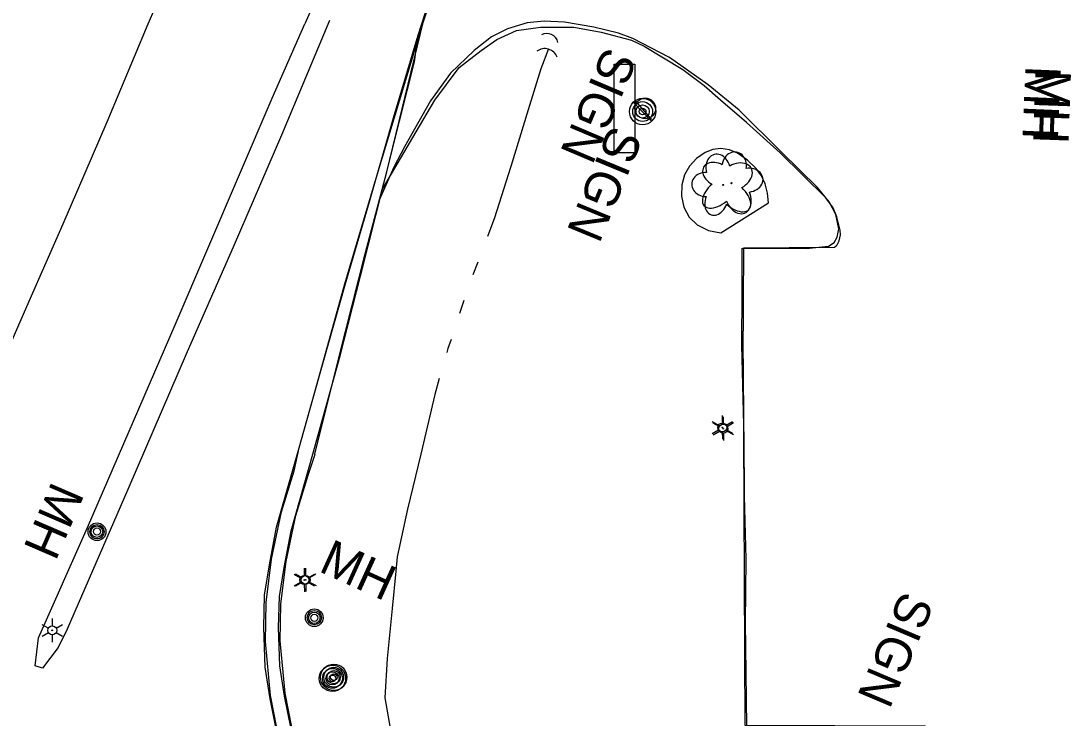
# Model space of a CAD drawing. Extents: x 588843 to 2552415, y 180129 to 269402.
# Drawn here: x 593439.1 to 593615.7, y 185837.6 to 185955.5 of the extents above; entities that cross this region are included whole.
import ezdxf

# ---------------------------------------------------------------- set-up
doc = ezdxf.new("R2010")
doc.units = 0
for name, color, linetype in [('Default', 7, 'Continuous'), ('E_DRN', 7, 'Continuous'), ('E_DWY', 7, 'Continuous'), ('E_LAND_Vegetation', 7, 'Continuous'), ('E_LTG', 7, 'Continuous'), ('E_MISCPROP', 7, 'Continuous'), ('E_MISCPROP_Planter', 7, 'Continuous'), ('E_RDWY', 7, 'Continuous'), ('E_RDWY_AsphConc', 7, 'Continuous'), ('E_RDWY_C_and_G', 7, 'Continuous'), ('E_RDWY_Gravel', 7, 'Continuous'), ('E_SGN', 7, 'Continuous'), ('E_SGN_Text', 7, 'Continuous'), ('E_UTL_MH', 7, 'Continuous'), ('E_UTL_MH_Text', 7, 'Continuous'), ('E_WTR_P', 7, 'Continuous')]:
    doc.layers.add(name, color=color, linetype=linetype)

# ---------------------------------------------------------------- blocks, each defined once
blk = doc.blocks.new('LPOL')
at = {"layer": 'Default'}
for p, q in [((-4, 0), (-1.5, 0)), ((-0.75, 1.3), (-2, 3.46)), ((0.75, 1.3), (2, 3.46)), ((1.5, 0), (4, 0)), ((-2, -3.46), (-0.75, -1.3)), ((2, -3.46), (0.75, -1.3))]:
    blk.add_line(p, q, dxfattribs=at)
for radius in [1.5, 1.5, 1.5, 0.125]:
    blk.add_circle((0, 0), radius, dxfattribs=at)
blk = doc.blocks.new('POLE')
at = {"layer": 'Default'}
for radius in [4.46, 3.35, 2.23, 1.12]:
    blk.add_circle((0, 0), radius, dxfattribs=at)
blk = doc.blocks.new('MHO')
at = {"layer": 'Default'}
for centre, radius in [((0.08, -0.12), 3), ((0.08, -0.12), 2.43), ((0.07, -0.15), 1.94), ((0.02, -0.16), 1.21)]:
    blk.add_circle(centre, radius, dxfattribs=at)
blk = doc.blocks.new('MHT')
at = {"layer": 'E_UTL_MH_Text'}
blk.add_text('MH', height=12, dxfattribs=at).set_placement((-9.81, -6))
blk = doc.blocks.new('SIGN')
at = {"layer": 'Default'}
blk.add_text('SIGN', height=12, dxfattribs=at).set_placement((-18.55, -6))
blk = doc.blocks.new('CULV2')
at = {"layer": 'E_DRN'}
blk.add_arc((19.7, 14.8), 24.6, 216.8699, 323.1301, dxfattribs=at)
blk = doc.blocks.new('DTRE_1_1')
at = {"layer": 'Default'}
blk.add_circle((-0.18, 0), 0.183, dxfattribs=at)
for centre, major_axis, ratio in [((-1.87, 5.32), (1.36, -4.98), 0.782863), ((4.06, 2.74), (-5.27, -2.93), 0.691916), ((-5.87, 0.15), (4.93, -0.12), 0.832022), ((3.54, -3.71), (-5.01, 4.58), 0.560249), ((-2.49, -5.24), (1.8, 4.86), 0.716896)]:
    blk.add_ellipse(centre, major_axis=major_axis, ratio=ratio, start_param=1.570796, end_param=4.712389, dxfattribs=at)
blk = doc.blocks.new('SGN_1')
at = {"layer": 'Default'}
blk.add_lwpolyline([(-3.5, -15), (-10.5, -15), (-10.5, 15), (-3.5, 15)], close=True, dxfattribs=at)
blk.add_circle((0, 0), 3.5, dxfattribs=at)
blk = doc.blocks.new('CULV2_4')
at = {"layer": 'E_DRN'}
blk.add_arc((64.6, 48.4), 80.7, 216.8699, 323.1301, dxfattribs=at)
blk = doc.blocks.new('MHO_3')
at = {"layer": 'E_UTL_MH'}
for centre, radius in [((0.3, -0.4), 9.84), ((0.3, -0.4), 7.98), ((0.2, -0.5), 6.35), ((0.1, -0.5), 3.97)]:
    blk.add_circle(centre, radius, dxfattribs=at)
blk = doc.blocks.new('MHT_3')
at = {"layer": 'E_UTL_MH_Text'}
blk.add_text('MH', height=39.37, dxfattribs=at).set_placement((-32.2, -19.7))
blk = doc.blocks.new('LPOL_4')
at = {"layer": 'E_LTG'}
for p, q in [((-13.1, 0), (-4.9, 0)), ((-2.5, 4.3), (-6.6, 11.4)), ((2.5, 4.3), (6.6, 11.4)), ((4.9, 0), (13.1, 0)), ((-6.6, -11.4), (-2.5, -4.3)), ((6.6, -11.4), (2.5, -4.3))]:
    blk.add_line(p, q, dxfattribs=at)
for radius in [4.92, 4.92, 4.92, 0.41]:
    blk.add_circle((0, 0), radius, dxfattribs=at)
blk = doc.blocks.new('POLE_3')
at = {"layer": 'E_MISCPROP'}
for radius in [14.6, 11, 7.32, 3.66]:
    blk.add_circle((0, 0), radius, dxfattribs=at)
blk = doc.blocks.new('SIGN_3')
at = {"layer": 'E_SGN'}
blk.add_text('SIGN', height=39.37, dxfattribs=at).set_placement((-56.1, -19.7))
blk = doc.blocks.new('DTRE_4')
at = {"layer": 'E_LAND_Vegetation'}
blk.add_circle((-0.6, 0), 0.601, dxfattribs=at)
for centre, major_axis, ratio in [((-6.1, 17.5), (4.5, -16.3), 0.782863), ((13.3, 9), (-17.3, -9.6), 0.691916), ((-19.3, 0.5), (16.2, -0.4), 0.832022), ((11.6, -12.2), (-16.4, 15), 0.560249), ((-8.2, -17.2), (5.9, 15.9), 0.716896)]:
    blk.add_ellipse(centre, major_axis=major_axis, ratio=ratio, start_param=1.570796, end_param=4.712389, dxfattribs=at)

msp = doc.modelspace()

# ---------------------------------------------------------------- linework, layer by layer
at = {"layer": 'E_DWY'}
for points in [[(593561.94, 185836.17), (593561.79, 185845.33), (593561.7, 185853.71), (593561.78, 185864.51), (593561.53, 185875.2), (593561.46, 185884.92), (593561.05, 185900.77), (593561.15, 185909.64), (593561.13, 185917.12), (593571.94, 185917.04), (593575.75, 185917.43), (593576.69, 185918.07), (593577.21, 185918.97), (593577.49, 185920.35), (593576.96, 185922.82), (593575.82, 185924.96), (593573.84, 185927.35), (593567.73, 185933.39), (593560.63, 185940.47), (593555.38, 185944.71), (593548.82, 185949.37), (593542.62, 185952.54), (593540.2, 185953.46), (593536.05, 185954.48), (593531.09, 185955.31), (593527.62, 185955.49), (593524.78, 185955.24), (593521.41, 185954.22), (593518.74, 185952.83), (593515.8, 185950.54), (593511.77, 185946.7), (593508.42, 185942.02), (593503.99, 185934.26), (593502.21, 185930.8), (593499.75, 185925.22)], [(593500.29, 185927.09), (593505.98, 185936.79), (593509.15, 185942.13), (593513.24, 185947.65), (593516.99, 185950.55), (593519.61, 185952.39), (593522.93, 185953.92), (593527.03, 185954.47), (593532.67, 185954.47), (593537.25, 185953.63), (593542.38, 185952.3), (593544.53, 185951.27)], [(593561.3, 185898.37), (593561.59, 185836.43), (593592.09, 185836.3), (593585.32, 185824.31), (593579.2, 185807.78), (593629.08, 185786.97), (593683.34, 185763.77), (593715.78, 185763.83), (593758.03, 185763.57), (593758.13, 185803.19), (593757.72, 185847.98), (593757.71, 185903.71), (593757.53, 185954.3)]]:
    msp.add_lwpolyline(points, dxfattribs=at)
at = {"layer": 'E_MISCPROP_Planter'}
msp.add_lwpolyline([(593565.57, 185924.78), (593565.42, 185926.41), (593565.01, 185927.99), (593565.01, 185927.99), (593564.38, 185929.35), (593563.51, 185930.58), (593563.51, 185930.58), (593562.04, 185932.01), (593560.34, 185933.17), (593560.34, 185933.17), (593558.98, 185933.73), (593557.52, 185933.94), (593557.52, 185933.94), (593556.15, 185933.78), (593554.86, 185933.27), (593554.86, 185933.27), (593553.42, 185932.26), (593552.23, 185930.98), (593552.23, 185930.98), (593551.38, 185929.49), (593550.93, 185927.83), (593550.93, 185927.83), (593550.89, 185925.92), (593551.28, 185924.05), (593551.28, 185924.05), (593552.16, 185922.36), (593553.53, 185921.03), (593553.53, 185921.03), (593555.44, 185920.08), (593557.53, 185919.71), (593557.53, 185919.71)], close=True, dxfattribs=at)
at = {"layer": 'E_RDWY'}
for points in [[(593486.2, 185883.3), (593489.18, 185893.96), (593493.89, 185911.07), (593499.24, 185928.93), (593507.1, 185955.12), (593509.61, 185962.65), (593517.48, 185983.79), (593527.72, 186012.54), (593531.1, 186022.16), (593535.59, 186036.96), (593539.47, 186051.68), (593541.2, 186062.67), (593545.15, 186089.33), (593548.03, 186107.77), (593551.11, 186127.76), (593554.74, 186154.6), (593556.82, 186170.65)], [(593460.64, 185955.04), (593467.37, 185970.47), (593472.37, 185982.97), (593477.68, 185995.79), (593482.62, 186008.82), (593487.75, 186022.71), (593492.35, 186036.69), (593496.3, 186049.62), (593500.01, 186061.89)], [(593522.56, 186054.59), (593521.25, 186049.62), (593517.22, 186036.16), (593512.49, 186021.93), (593508.45, 186009.64), (593504.16, 185997.05), (593500.25, 185987.06), (593494.6, 185972.85), (593489.15, 185959.57), (593487.18, 185955.06)], [(593506.3, 185953.15), (593509.39, 185962.62), (593513.59, 185974.38), (593520.05, 185991.23), (593526.18, 186009.1), (593530.36, 186021.24), (593534.44, 186034.67), (593538.07, 186046.79), (593539.46, 186052.49)], [(593491.32, 185955.6), (593483.2, 185936.21), (593475.03, 185917.29), (593467.27, 185899.56), (593457.19, 185876.3), (593446.96, 185852.66), (593445.45, 185849.57), (593442.79, 185846.03), (593441.53, 185846.44), (593442.11, 185851.19), (593450.4, 185869.87), (593465.24, 185904.11), (593481.63, 185942.45), (593487.18, 185955.06)], [(593426.69, 185881.38), (593434.16, 185893.64), (593440.51, 185908.11), (593446.3, 185921.2), (593453.72, 185938.48), (593460.64, 185955.04)], [(593486.07, 185882.94), (593490.12, 185897.35), (593494.11, 185911.31), (593497.9, 185924.36), (593502.15, 185939.12), (593506.3, 185953.15)]]:
    msp.add_lwpolyline(points, dxfattribs=at)
at = {"layer": 'E_RDWY_AsphConc'}
for points in [[(593575.28, 185925.62), (593567.53, 185933.21), (593567.53, 185933.21), (593561.85, 185938.36), (593561.85, 185938.36), (593557.47, 185942.16), (593557.47, 185942.16), (593554.67, 185944.56), (593554.67, 185944.56), (593551.1, 185947.24), (593551.1, 185947.24), (593544.53, 185951.21), (593544.53, 185951.21)], [(593561.32, 185898.38), (593561.43, 185917.13), (593576.75, 185917.25), (593577.04, 185917.48), (593577.04, 185917.48), (593577.19, 185917.64), (593577.19, 185917.64), (593577.55, 185918.35), (593577.55, 185918.35), (593577.76, 185919.33), (593577.76, 185919.33), (593577.71, 185920.14), (593577.71, 185920.14), (593577.15, 185922.41), (593577.15, 185922.41), (593576.5, 185923.9), (593576.5, 185923.9), (593575.28, 185925.62), (593575.28, 185925.62)]]:
    msp.add_lwpolyline(points, dxfattribs=at)
at = {"layer": 'E_RDWY_C_and_G'}
for points in [[(593524.54, 185785.23), (593520.46, 185787.18), (593514.54, 185790.64), (593509.77, 185793.89), (593504.56, 185798.16), (593499.13, 185803.52), (593495.33, 185808.28), (593491.66, 185813.55), (593488.12, 185819.59), (593485.79, 185824.76), (593484.01, 185829.67), (593482.39, 185835.21), (593481.28, 185840.87), (593480.44, 185846.23), (593480.21, 185852.92), (593480.35, 185858.38), (593481.19, 185863.53), (593482.38, 185869.88), (593486.07, 185882.94)], [(593525.28, 185784.5), (593516.08, 185789.89), (593507.12, 185796.18), (593500.49, 185802.26), (593495.89, 185807.55), (593491.73, 185813.52), (593488.45, 185819.36), (593485.74, 185825.44), (593482.99, 185833.08), (593481.36, 185841.45), (593480.5, 185850.56), (593480.6, 185857.14), (593481.52, 185864.5), (593483.18, 185872.5), (593485.32, 185879.46), (593486.2, 185883.3)], [(593525.62, 185787.49), (593521.63, 185789.39), (593515.87, 185792.75), (593511.27, 185795.89), (593506.24, 185800.02), (593501, 185805.19), (593497.34, 185809.78), (593493.77, 185814.9), (593490.34, 185820.74), (593488.11, 185825.7), (593486.38, 185830.45), (593484.82, 185835.81), (593483.74, 185841.3), (593482.93, 185846.46), (593482.71, 185852.93), (593482.84, 185858.15), (593483.65, 185863.1), (593484.82, 185869.31), (593488.48, 185882.26)], [(593526.49, 185787.32), (593517.38, 185792.03), (593508.69, 185798.13), (593502.28, 185804.01), (593497.86, 185809.09), (593493.85, 185814.85), (593490.68, 185820.48), (593488.06, 185826.38), (593485.4, 185833.75), (593483.84, 185841.81), (593483, 185850.66), (593483.1, 185856.96), (593483.98, 185864.09), (593485.61, 185871.88), (593487.7, 185878.69), (593488.91, 185882.24)]]:
    msp.add_lwpolyline(points, dxfattribs=at)
at = {"layer": 'E_RDWY_Gravel'}
for points in [[(593488.82, 185882.27), (593492.95, 185898.78), (593497.36, 185916.15), (593501.01, 185930), (593507.22, 185955.48)], [(593488.48, 185882.26), (593493.13, 185898.88), (593496.57, 185912.37), (593500.46, 185927.75), (593501.95, 185933.67), (593505.72, 185948.6), (593506.3, 185953.15)]]:
    msp.add_lwpolyline(points, dxfattribs=at)
at = {"layer": 'E_SGN'}
msp.add_line((593542.99, 185942.1), (593545.78, 185938.85), dxfattribs=at)
msp.add_lwpolyline([(593545.86, 185938.52), (593542.72, 185941.73)], dxfattribs=at)
at = {"layer": 'E_WTR_P'}
for points in [[(593528.34, 185950.83), (593527.05, 185947.41), (593524.91, 185940.5), (593521.98, 185930.9), (593519.17, 185922.06), (593518.03, 185919.05)], [(593516.39, 185914.74), (593515.57, 185912.58)], [(593514.06, 185908.23), (593513.33, 185906.04)], [(593511.88, 185901.66), (593511.36, 185900.1), (593511.18, 185899.47)], [(593509.9, 185895.03), (593509.12, 185892.32), (593506.77, 185882.26), (593504.49, 185872.96), (593502.78, 185864.91), (593502.54, 185862.44)], [(593502.54, 185862.44), (593501.94, 185856.15), (593501.07, 185847.66), (593500.71, 185841.06), (593501.59, 185835.88), (593503.3, 185829.7), (593503.38, 185829.42)]]:
    msp.add_lwpolyline(points, dxfattribs=at)

# ---------------------------------------------------------------- block references
at = {"layer": 'E_DRN'}
for name, p, xscale, yscale, rotation in [('CULV2', (593529.97, 185951.92), 0.07740257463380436, 0.07740257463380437, 155.57690095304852), ('CULV2_4', (593529.84, 185949.39), 0.027930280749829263, 0.027930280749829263, 163.57397236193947)]:
    msp.add_blockref(name, p, dxfattribs=dict(at, xscale=xscale, yscale=yscale, rotation=rotation))
at = {"layer": 'E_LAND_Vegetation', "xscale": 0.5, "yscale": 0.5}
msp.add_blockref('DTRE_1_1', (593558, 185927.8), dxfattribs=at)
at = {"layer": 'E_LAND_Vegetation', "xscale": 0.1524003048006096, "yscale": 0.1524003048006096, "rotation": -97.36026881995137}
msp.add_blockref('DTRE_4', (593559.32, 185928.01), dxfattribs=at)
at = {"layer": 'E_LTG'}
for name, p, xscale, yscale, rotation in [('LPOL', (593557.76, 185886.77), 0.5000000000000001, 0.5, -89.67337617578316), ('LPOL_4', (593557.93, 185886.56), 0.1524003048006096, 0.1524003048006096, -89.2544447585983), ('LPOL', (593487.06, 185860.97), 0.5000000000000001, 0.5, -89.67337617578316), ('LPOL_4', (593487.3, 185861), 0.1524003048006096, 0.1524003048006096, -89.2544447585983), ('LPOL', (593444.43, 185852.45), 0.5000000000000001, 0.5, -89.67337617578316)]:
    msp.add_blockref(name, p, dxfattribs=dict(at, xscale=xscale, yscale=yscale, rotation=rotation))
at = {"layer": 'E_MISCPROP'}
for name, p, xscale, yscale, rotation in [('POLE', (593544.29, 185940.21), 0.5000000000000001, 0.5, -92.40976933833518), ('POLE', (593491.82, 185844.33), 0.5000000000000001, 0.5, -89.67337617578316), ('POLE_3', (593492.04, 185844.52), 0.1524003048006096, 0.1524003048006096, -89.2544447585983)]:
    msp.add_blockref(name, p, dxfattribs=dict(at, xscale=xscale, yscale=yscale, rotation=rotation))
at = {"layer": 'E_SGN', "xscale": 0.5, "yscale": 0.5}
msp.add_blockref('SGN_1', (593544.73, 185940.74), dxfattribs=at)
at = {"layer": 'E_SGN_Text'}
for name, p, xscale, yscale, rotation in [('SIGN', (593537.06, 185941.71), 0.5000000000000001, 0.5000000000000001, -113.0414243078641), ('SIGN_3', (593538.39, 185929.09), 0.1524003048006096, 0.1524003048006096, -112.48143376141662), ('SIGN', (593587.31, 185849.65), 0.5, 0.5, -112.98358720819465)]:
    msp.add_blockref(name, p, dxfattribs=dict(at, xscale=xscale, yscale=yscale, rotation=rotation))
at = {"layer": 'E_UTL_MH'}
for name, p, xscale, yscale, rotation in [('MHO', (593452.07, 185869.14), 0.4999999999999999, 0.49999999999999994, -113.37414845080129), ('MHO_3', (593488.68, 185854.57), 0.1524003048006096, 0.15240030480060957, 69.36716486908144)]:
    msp.add_blockref(name, p, dxfattribs=dict(at, xscale=xscale, yscale=yscale, rotation=rotation))
at = {"layer": 'E_UTL_MH_Text'}
for name, p, xscale, yscale, rotation in [('MHT', (593611.84, 185943.01), 0.4999999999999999, 0.5, -92.35193223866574), ('MHT_3', (593613.59, 185942.33), 0.1524003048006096, 0.1524003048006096, -92.028784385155), ('MHT', (593445.24, 185872.17), 0.4999999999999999, 0.49999999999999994, -113.37414845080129), ('MHT_3', (593495.01, 185863.22), 0.15240030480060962, 0.15240030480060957, -24.440434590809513)]:
    msp.add_blockref(name, p, dxfattribs=dict(at, xscale=xscale, yscale=yscale, rotation=rotation))

doc.saveas('drawing.dxf')
